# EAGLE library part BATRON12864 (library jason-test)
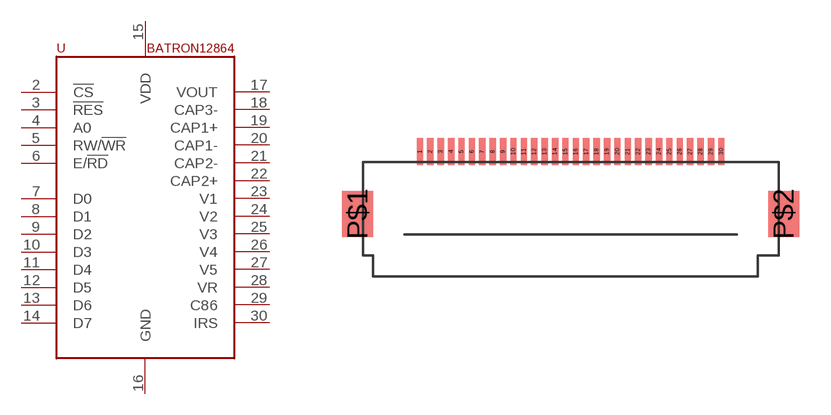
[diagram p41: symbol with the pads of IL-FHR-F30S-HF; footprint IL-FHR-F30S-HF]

Designator prefix -

## BATRON12864  [IL-FHR-F30S-HF]
2  !CS  in
3  !RES  in
4  A0  in
5  RW/!WR  in
6  E/!RD  in
7  D0
8  D1
9  D2
10  D3
11  D4
12  D5
13  D6
14  D7
15  VDD  pwr
16  GND  pwr
17  VOUT
18  CAP3-
19  CAP1+
20  CAP1-
21  CAP2-
22  CAP2+
23  V1
24  V2
25  V3
26  V4
27  V5
28  VR
29  C86  in
30  IRS  in

## Footprint IL-FHR-F30S-HF (pad centres in mm)
smd 0.3 x 1.3: 1 -7.25,0.5; 2 -6.75,0.5; 3 -6.25,0.5; 4 -5.75,0.5; 5 -5.25,0.5; 6 -4.75,0.5; 7 -4.25,0.5; 8 -3.75,0.5; 9 -3.25,0.5; 10 -2.75,0.5; 11 -2.25,0.5; 12 -1.75,0.5; 13 -1.25,0.5; 14 -0.75,0.5; 15 -0.25,0.5; 16 0.25,0.5; 17 0.75,0.5; 18 1.25,0.5; 19 1.75,0.5; 20 2.25,0.5; 21 2.75,0.5; 22 3.25,0.5; 23 3.75,0.5; 24 4.25,0.5; 25 4.75,0.5; 26 5.25,0.5; 27 5.75,0.5; 28 6.25,0.5; 29 6.75,0.5; 30 7.25,0.5
smd 1.5 x 2.2: P$1 -10.25,-2.5; P$2 10.25,-2.5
